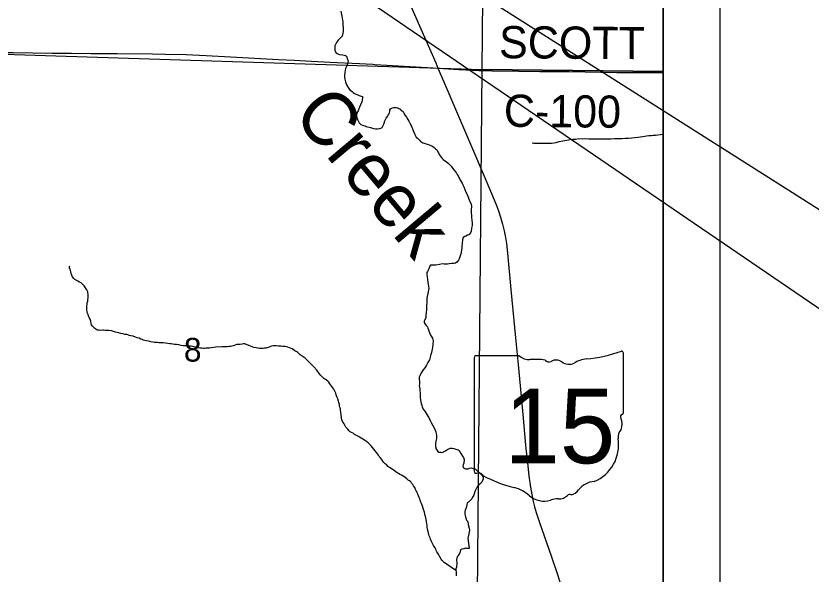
# Model space of a CAD drawing. Extents: x 0 to 34, y 0 to 22.
# Drawn here: x 7.757 to 9.161, y 14.502 to 15.487 of the extents above; entities that cross this region are included whole.
import ezdxf

# ---------------------------------------------------------------- set-up
doc = ezdxf.new("R2010")
doc.units = 0
for name, color, linetype in [('GM_X_County_Road', 7, 'Continuous'), ('GM_X_County_Road_Text', 7, 'Continuous'), ('GM_X_County_Text', 7, 'Continuous'), ('GM_X_Minor_River', 7, 'Continuous'), ('GM_X_Minor_River_Text', 7, 'Continuous'), ('GM_X_Rail_Line_Text', 7, 'Continuous'), ('GM_X_Section', 7, 'Continuous'), ('GM_X_Section_Text', 7, 'Continuous'), ('GM_X_State_Location', 7, 'Continuous'), ('GM_X_State_Route', 7, 'Continuous'), ('GM_X_State_Shield', 7, 'Continuous'), ('GM_X_Township_Road', 7, 'Continuous'), ('SH_Cut_Line', 7, 'Continuous'), ('SH_Data', 7, 'Continuous'), ('TX_P_1', 7, 'Continuous')]:
    doc.layers.add(name, color=color, linetype=linetype)

msp = doc.modelspace()

# ---------------------------------------------------------------- linework, layer by layer
at = {"layer": 'GM_X_County_Road'}
for points in [[(7.5713, 15.4236), (7.5782, 15.4235), (7.5987, 15.4232), (7.6392, 15.4233), (7.6746, 15.4228), (7.7138, 15.4224), (7.7523, 15.422), (7.8207, 15.4213), (7.855, 15.4212), (7.889, 15.4207), (7.9212, 15.4207), (7.9357, 15.4208), (7.9984, 15.42), (8.0208, 15.4192), (8.0575, 15.4185), (8.0929, 15.4171), (8.1357, 15.4146), (8.2207, 15.4099), (8.2487, 15.4086), (8.2791, 15.407), (8.3113, 15.4055)], [(8.3113, 15.4055), (8.3636, 15.4029), (8.3871, 15.4014), (8.3911, 15.4012)], [(8.3911, 15.4012), (8.412, 15.4), (8.4942, 15.395), (8.5024, 15.3946)], [(8.5024, 15.3946), (8.5395, 15.3922), (8.5525, 15.3917), (8.5632, 15.3912), (8.5744, 15.3907), (8.5863, 15.3903), (8.5979, 15.3899), (8.6454, 15.3892), (8.6821, 15.389), (8.7343, 15.3885), (8.8182, 15.3872), (8.8686, 15.3872), (8.8916, 15.3869), (8.9, 15.3868)]]:
    msp.add_lwpolyline(points, dxfattribs=at)
at = {"layer": 'GM_X_County_Text'}
msp.add_lwpolyline([(6.615, 14.1), (8.9, 14.1), (8.9, 16.3981)], dxfattribs=at)
at = {"layer": 'GM_X_Minor_River'}
for points in [[(8.3309, 15.4952), (8.3326, 15.4864), (8.3336, 15.4795), (8.3343, 15.4768), (8.3345, 15.4723), (8.3351, 15.4647), (8.335, 15.4593), (8.3345, 15.4567), (8.3333, 15.451), (8.3302, 15.4481), (8.3278, 15.4458), (8.3263, 15.444), (8.3247, 15.4421), (8.3231, 15.4399), (8.3212, 15.4365), (8.3203, 15.4342), (8.3203, 15.4319), (8.3202, 15.4293), (8.3205, 15.4262), (8.3223, 15.4224), (8.3246, 15.4208), (8.328, 15.4189), (8.3336, 15.418), (8.3367, 15.4175), (8.3389, 15.4171), (8.3408, 15.4159), (8.3425, 15.4098), (8.3436, 15.4078), (8.3419, 15.3999), (8.3391, 15.3943), (8.3378, 15.3871), (8.3373, 15.3818), (8.3376, 15.378), (8.3379, 15.3753), (8.339, 15.3707), (8.3411, 15.3653), (8.3437, 15.3603), (8.3462, 15.3572), (8.3485, 15.3553), (8.3507, 15.3533), (8.3529, 15.3514), (8.3548, 15.3502), (8.3589, 15.3482), (8.3608, 15.3474), (8.3631, 15.3462), (8.365, 15.3458), (8.3668, 15.345), (8.3691, 15.3445), (8.369, 15.3419)], [(8.369, 15.3419), (8.3681, 15.3354), (8.3657, 15.3298), (8.3641, 15.326), (8.3629, 15.3226), (8.3617, 15.3193), (8.3601, 15.3174), (8.3589, 15.3144), (8.3585, 15.3125), (8.3584, 15.3106), (8.3591, 15.3072), (8.3602, 15.3041), (8.3616, 15.3014), (8.3635, 15.2983), (8.3661, 15.2952), (8.3694, 15.294), (8.3717, 15.2932), (8.374, 15.2927), (8.3758, 15.2919), (8.3781, 15.2911), (8.3811, 15.2903), (8.3834, 15.2899), (8.3853, 15.2891), (8.3883, 15.2882), (8.3921, 15.2874), (8.3959, 15.2873), (8.3997, 15.288), (8.4016, 15.2887), (8.4039, 15.2901), (8.4059, 15.2935), (8.4067, 15.2958), (8.4079, 15.2992), (8.4087, 15.3014), (8.4095, 15.3041), (8.4107, 15.3063), (8.4131, 15.3093), (8.4143, 15.3116), (8.4158, 15.3134), (8.417, 15.316), (8.4175, 15.3183), (8.4175, 15.321), (8.4187, 15.3228), (8.4206, 15.3239), (8.4245, 15.325), (8.4286, 15.3253), (8.4313, 15.3245), (8.4332, 15.3236), (8.4354, 15.3221), (8.4376, 15.3201), (8.4395, 15.3186), (8.4413, 15.3166), (8.4428, 15.3143), (8.4446, 15.3112), (8.4468, 15.3081), (8.4494, 15.3039), (8.4512, 15.3008), (8.453, 15.2973), (8.4548, 15.2935), (8.4595, 15.2816), (8.4617, 15.2774), (8.4642, 15.2731), (8.4661, 15.2708), (8.4679, 15.2692), (8.4698, 15.2673), (8.4716, 15.2654), (8.4739, 15.2638), (8.4758, 15.263), (8.478, 15.2622), (8.4818, 15.2609), (8.4859, 15.2597), (8.4886, 15.2589), (8.4908, 15.2577), (8.4927, 15.2569), (8.4957, 15.2545), (8.4979, 15.2522), (8.5002, 15.2506), (8.5023, 15.2472), (8.5034, 15.2452), (8.5045, 15.2422), (8.5064, 15.2398), (8.5078, 15.2375), (8.5097, 15.2352), (8.5115, 15.2336), (8.5141, 15.2317), (8.5171, 15.2301), (8.5205, 15.227), (8.5227, 15.2246), (8.5257, 15.2215), (8.5282, 15.218), (8.5312, 15.2146), (8.5334, 15.2115), (8.5353, 15.2095), (8.5363, 15.2072), (8.5378, 15.2045), (8.5392, 15.2018), (8.5403, 15.1999), (8.5411, 15.198), (8.5451, 15.1914), (8.5462, 15.1887), (8.548, 15.1849), (8.5498, 15.1807)], [(8.669, 15.2626), (8.6694, 15.2626), (8.6716, 15.2625), (8.6758, 15.2624), (8.6796, 15.2623), (8.688, 15.2621), (8.691, 15.2621), (8.6959, 15.262), (8.6997, 15.2622), (8.7032, 15.2625), (8.707, 15.2628), (8.7112, 15.2635), (8.7165, 15.2649), (8.723, 15.2666), (8.7299, 15.2676), (8.736, 15.2686), (8.7413, 15.2692), (8.7458, 15.2695), (8.7512, 15.2702), (8.758, 15.27), (8.7633, 15.2702), (8.769, 15.2701), (8.7751, 15.27), (8.7812, 15.2698), (8.7872, 15.2697), (8.7933, 15.2699), (8.7982, 15.2698), (8.8032, 15.2701), (8.8085, 15.2699), (8.8142, 15.2702), (8.8218, 15.2704), (8.8275, 15.2706), (8.8332, 15.2709), (8.8389, 15.2711), (8.8446, 15.2714), (8.8503, 15.272), (8.8556, 15.273), (8.8602, 15.2737), (8.864, 15.2743), (8.8678, 15.2746), (8.8709, 15.2753), (8.8747, 15.2756), (8.8796, 15.2759), (8.8827, 15.2762), (8.8865, 15.2765), (8.8907, 15.2767), (8.8952, 15.2774), (8.9, 15.2784)], [(8.5498, 15.1807), (8.5515, 15.1757), (8.5541, 15.1715), (8.5559, 15.1672), (8.558, 15.1607), (8.5606, 15.1561), (8.5616, 15.1508), (8.5611, 15.1443), (8.561, 15.1409), (8.5615, 15.1321), (8.5621, 15.1253), (8.5628, 15.1222), (8.5627, 15.1169), (8.5618, 15.112), (8.5613, 15.1067), (8.5597, 15.1037), (8.557, 15.1007), (8.5547, 15.0996), (8.5516, 15.0982), (8.5497, 15.0978), (8.547, 15.0956), (8.5458, 15.0918), (8.5444, 15.0801), (8.5443, 15.0774), (8.5442, 15.0733), (8.5429, 15.0672), (8.5413, 15.0616), (8.5397, 15.0582), (8.5388, 15.0555), (8.5357, 15.0522), (8.5334, 15.0503), (8.5304, 15.05), (8.5269, 15.0497), (8.5224, 15.0491), (8.5193, 15.0488), (8.5167, 15.0488), (8.5136, 15.0489), (8.5106, 15.049), (8.5053, 15.048), (8.4988, 15.047), (8.4931, 15.0471), (8.4893, 15.0472), (8.4881, 15.0453), (8.4861, 15.0404), (8.4837, 15.0359), (8.4825, 15.0341), (8.4828, 15.0299), (8.4835, 15.0261), (8.4841, 15.0215), (8.4848, 15.0162), (8.4851, 15.0131), (8.4858, 15.0097), (8.4861, 15.0062), (8.4856, 15.0032), (8.4851, 14.9998), (8.4826, 14.9888), (8.4829, 14.9866), (8.4828, 14.9812), (8.4823, 14.9748), (8.4821, 14.9683), (8.4816, 14.9634), (8.4812, 14.9592), (8.4807, 14.9547), (8.4794, 14.9502), (8.4782, 14.9479), (8.4782, 14.946), (8.4796, 14.9429), (8.4815, 14.9402), (8.4837, 14.9383), (8.4844, 14.936), (8.489, 14.9233), (8.4927, 14.9183), (8.4941, 14.9133), (8.4927, 14.9016), (8.491, 14.8925), (8.4898, 14.8891), (8.4873, 14.8797), (8.4845, 14.8752), (8.4821, 14.8703), (8.479, 14.8658), (8.4762, 14.8621), (8.4739, 14.8587), (8.4723, 14.8557), (8.4711, 14.8535), (8.4703, 14.8516), (8.4695, 14.8493), (8.4694, 14.8463), (8.4697, 14.8417), (8.4696, 14.8371), (8.4695, 14.8345), (8.4698, 14.8314), (8.4701, 14.8284), (8.4704, 14.8257), (8.4707, 14.8212), (8.4709, 14.8132), (8.4715, 14.8086), (8.4722, 14.8055), (8.4729, 14.8029), (8.474, 14.7998), (8.4747, 14.7967), (8.4765, 14.7925)], [(8.0524, 14.9048), (8.049, 14.9052), (8.0448, 14.9061), (8.0407, 14.9066), (8.0373, 14.907), (8.0339, 14.9075), (8.0312, 14.9079), (8.0286, 14.908), (8.0252, 14.9089), (8.021, 14.9093), (8.0168, 14.9098), (8.013, 14.9099), (8.0096, 14.91), (8.007, 14.9104), (8.0047, 14.9105), (8.0017, 14.9105), (7.9986, 14.911), (7.9952, 14.9118), (7.9933, 14.9119), (7.9911, 14.9127), (7.9869, 14.9136), (7.9824, 14.9148), (7.9798, 14.9156), (7.9775, 14.9164), (7.9749, 14.918), (7.9711, 14.9189), (7.9681, 14.9201), (7.9643, 14.9213), (7.9602, 14.9222), (7.9572, 14.923), (7.9549, 14.9238), (7.9526, 14.9243), (7.9496, 14.9247), (7.9462, 14.9255), (7.9424, 14.9264), (7.9379, 14.9276), (7.9326, 14.9289), (7.9292, 14.9301), (7.9255, 14.931), (7.9213, 14.9315), (7.9179, 14.9315), (7.9145, 14.9316), (7.9118, 14.9321), (7.9099, 14.9321), (7.9069, 14.9314), (7.9042, 14.9319), (7.9012, 14.9323), (7.8986, 14.9335), (7.8956, 14.9355), (7.8937, 14.9374), (7.8919, 14.9398), (7.8904, 14.9417), (7.8901, 14.9436), (7.889, 14.9478), (7.888, 14.9516), (7.8865, 14.9547), (7.8854, 14.9566), (7.8844, 14.9597), (7.883, 14.9635), (7.8826, 14.9654), (7.8823, 14.9673), (7.882, 14.9696), (7.882, 14.9715), (7.8821, 14.9746), (7.8825, 14.978), (7.883, 14.9806), (7.8838, 14.9836), (7.8842, 14.9863), (7.8843, 14.9893), (7.8844, 14.992), (7.8844, 14.9939), (7.8838, 14.9996), (7.882, 15.0034), (7.8798, 15.0069), (7.8776, 15.0104), (7.8746, 15.0131), (7.872, 15.0155), (7.869, 15.0171), (7.8664, 15.0186), (7.8612, 15.0218), (7.8593, 15.0234), (7.8567, 15.0261), (7.8557, 15.0295), (7.8546, 15.0322), (7.8539, 15.0349), (7.8532, 15.0376), (7.8525, 15.0399), (7.8518, 15.0418), (7.8515, 15.0448), (7.8519, 15.0456)], [(8.3365, 14.7666), (8.3347, 14.7693), (8.3325, 14.7735), (8.3322, 14.7777), (8.3316, 14.7826), (8.331, 14.7872), (8.3303, 14.791), (8.33, 14.7941), (8.3293, 14.7964), (8.3286, 14.7987), (8.3282, 14.801), (8.3276, 14.8044), (8.3265, 14.8071), (8.3258, 14.8109), (8.3244, 14.8136), (8.3233, 14.8163), (8.3226, 14.8182), (8.3219, 14.8209), (8.3204, 14.8243), (8.3182, 14.8282), (8.3116, 14.8375), (8.3098, 14.8402), (8.3076, 14.8421), (8.305, 14.8445), (8.3027, 14.8457), (8.3008, 14.8468), (8.2982, 14.8492), (8.2956, 14.8519), (8.2927, 14.8558), (8.2883, 14.8616), (8.2831, 14.8674), (8.2779, 14.8728), (8.2727, 14.8779), (8.2679, 14.883), (8.2623, 14.8861), (8.2589, 14.8889), (8.2567, 14.8908), (8.2548, 14.8928), (8.253, 14.894), (8.2496, 14.8959), (8.2474, 14.8975), (8.2447, 14.8991), (8.2421, 14.9003), (8.2402, 14.9011), (8.2372, 14.9019), (8.2346, 14.9027), (8.2319, 14.9032), (8.2285, 14.9036), (8.2247, 14.9037), (8.221, 14.9042), (8.2168, 14.9043), (8.2137, 14.9044), (8.2115, 14.9044), (8.2084, 14.9037), (8.2057, 14.9027), (8.2027, 14.9016), (8.2, 14.9009), (8.1981, 14.9006), (8.1958, 14.9002), (8.1939, 14.8999), (8.1912, 14.9), (8.1893, 14.9), (8.1871, 14.9001), (8.1844, 14.9005), (8.181, 14.901), (8.1772, 14.9018), (8.1712, 14.9039), (8.1614, 14.9079), (8.1588, 14.9083), (8.1565, 14.9073), (8.1531, 14.907), (8.15, 14.9066), (8.1474, 14.9067), (8.1443, 14.9056), (8.1424, 14.9049), (8.1405, 14.9046), (8.1382, 14.9039), (8.1359, 14.9036), (8.1336, 14.9032), (8.1306, 14.9029), (8.1283, 14.9026), (8.1256, 14.9027), (8.1215, 14.9028), (8.1101, 14.9023), (8.1059, 14.9016), (8.1017, 14.901), (8.0986, 14.9006), (8.0952, 14.9003), (8.0922, 14.9004), (8.0899, 14.9001), (8.0876, 14.9001), (8.0846, 14.9002), (8.0819, 14.9007), (8.0789, 14.9011), (8.0751, 14.902), (8.071, 14.9028), (8.0664, 14.9037), (8.0626, 14.9042), (8.0592, 14.9046), (8.0554, 14.9047), (8.0524, 14.9048)], [(8.4765, 14.7925), (8.4791, 14.789), (8.4809, 14.7863), (8.4827, 14.7836), (8.4846, 14.7806), (8.4864, 14.7778), (8.4889, 14.7725), (8.4911, 14.7679), (8.4933, 14.764), (8.4955, 14.7598), (8.4973, 14.7559), (8.4987, 14.7525), (8.4994, 14.7494), (8.4997, 14.7468), (8.5, 14.7437), (8.4996, 14.7411), (8.4991, 14.7388), (8.4987, 14.7358), (8.4982, 14.7327), (8.4982, 14.7297), (8.4981, 14.727), (8.4984, 14.7251), (8.4988, 14.7232), (8.5021, 14.7182), (8.5039, 14.717), (8.507, 14.7166), (8.5089, 14.7165), (8.5108, 14.7169), (8.5134, 14.7179), (8.5158, 14.7194), (8.5181, 14.7212), (8.5204, 14.7223), (8.5227, 14.7234), (8.5246, 14.7237), (8.5273, 14.7241), (8.5303, 14.7236), (8.5337, 14.722), (8.5378, 14.7208), (8.5397, 14.7196), (8.5426, 14.7146), (8.5455, 14.7099), (8.5477, 14.7072), (8.5488, 14.7038), (8.5479, 14.6977), (8.5471, 14.6947), (8.5466, 14.6924), (8.5473, 14.6894), (8.5511, 14.6874), (8.5537, 14.6873), (8.5556, 14.6877), (8.5583, 14.6887), (8.5617, 14.689), (8.5644, 14.6882), (8.5663, 14.6878), (8.5689, 14.6866), (8.5782, 14.678), (8.5804, 14.6757), (8.5822, 14.6726), (8.5822, 14.6696), (8.5813, 14.6669), (8.5798, 14.6639), (8.5766, 14.6606), (8.5739, 14.6584), (8.5716, 14.6558), (8.5696, 14.652), (8.5676, 14.6475), (8.5656, 14.6411), (8.5636, 14.6373), (8.562, 14.6347), (8.5589, 14.631), (8.5561, 14.6284), (8.5538, 14.6277), (8.5534, 14.6239), (8.5521, 14.6186), (8.5505, 14.6144), (8.5497, 14.6118), (8.55, 14.6072), (8.551, 14.6027), (8.5531, 14.5969), (8.555, 14.5942), (8.5556, 14.5892), (8.5577, 14.5827), (8.558, 14.5793), (8.5571, 14.5729), (8.5559, 14.5676), (8.5554, 14.5653), (8.5573, 14.547), (8.5554, 14.5467), (8.5523, 14.5471), (8.5504, 14.5472), (8.5481, 14.5465), (8.5447, 14.5454), (8.542, 14.5443), (8.5408, 14.5394), (8.538, 14.5342), (8.5356, 14.5304), (8.5352, 14.5266), (8.5358, 14.5209), (8.5352, 14.5141), (8.534, 14.5107), (8.5339, 14.5077)], [(8.5339, 14.5077), (8.5134, 14.5222), (8.5112, 14.5246), (8.5093, 14.5261), (8.5082, 14.528), (8.506, 14.5319), (8.5042, 14.5354), (8.502, 14.5388), (8.5006, 14.5411), (8.4995, 14.5435), (8.4988, 14.5458), (8.4973, 14.5481), (8.4958, 14.5504), (8.4948, 14.5523), (8.4929, 14.5558), (8.4911, 14.5592), (8.4893, 14.5631), (8.4886, 14.5654), (8.4868, 14.5692), (8.4861, 14.5715), (8.4854, 14.5746), (8.4847, 14.5784), (8.4841, 14.5818), (8.4834, 14.5841), (8.4834, 14.586), (8.4831, 14.5879), (8.4827, 14.5906), (8.4814, 14.5982), (8.4807, 14.6009), (8.48, 14.6051), (8.4787, 14.6108), (8.4769, 14.6154), (8.4755, 14.62), (8.4744, 14.6235), (8.4733, 14.6262), (8.4723, 14.6288), (8.4712, 14.6319), (8.4701, 14.6342), (8.4694, 14.6369), (8.4683, 14.6396), (8.4672, 14.6415), (8.4665, 14.6438), (8.4654, 14.6461), (8.464, 14.6484), (8.4629, 14.6511), (8.4615, 14.6542), (8.4593, 14.6576), (8.4578, 14.66), (8.4559, 14.6619), (8.4545, 14.6642), (8.4519, 14.6662), (8.45, 14.6677), (8.4474, 14.6697), (8.4437, 14.6728), (8.4411, 14.6744), (8.4381, 14.6764), (8.4351, 14.6776), (8.4328, 14.6792), (8.4306, 14.6804), (8.428, 14.6823), (8.4257, 14.6839), (8.4231, 14.6859), (8.4205, 14.6874), (8.4179, 14.689), (8.4156, 14.6906), (8.4137, 14.6918), (8.4119, 14.6937), (8.4093, 14.6964), (8.4067, 14.6988), (8.4049, 14.7011), (8.4034, 14.7038), (8.4001, 14.7073), (8.3986, 14.7092), (8.3971, 14.7116), (8.3957, 14.7139), (8.3938, 14.7162), (8.3916, 14.7193), (8.389, 14.7224), (8.3868, 14.7251), (8.3846, 14.7278), (8.3813, 14.7309), (8.379, 14.7333), (8.3761, 14.7356), (8.3727, 14.738), (8.3697, 14.7399), (8.3667, 14.7415), (8.3641, 14.7431), (8.3618, 14.7443), (8.3596, 14.7455), (8.3573, 14.7471), (8.3547, 14.7483), (8.3525, 14.7502), (8.3495, 14.7514), (8.3476, 14.753), (8.3458, 14.7546), (8.3435, 14.7573), (8.3417, 14.7592), (8.3398, 14.7612), (8.3384, 14.7635), (8.3365, 14.7666)], [(8.5339, 14.5077), (8.5343, 14.5054), (8.5346, 14.502), (8.5345, 14.4985)]]:
    msp.add_lwpolyline(points, dxfattribs=at)
at = {"layer": 'GM_X_Rail_Line_Text'}
for points in [[(8.9, 15.3885), (8.9, 16.3968), (8.5987, 16.4027), (8.5893, 16.4029), (8.5798, 15.3924)], [(8.9, 14.393), (8.9, 15.3885), (8.5798, 15.3924), (8.5711, 14.3987)]]:
    msp.add_lwpolyline(points, close=True, dxfattribs=at)
at = {"layer": 'GM_X_Section'}
msp.add_lwpolyline([(7.5704, 15.4246), (8.5798, 15.3924), (8.5711, 14.3987), (7.5551, 14.4246)], close=True, dxfattribs=at)
at = {"layer": 'GM_X_State_Route'}
for points in [[(8.4259, 15.5698), (8.4898, 15.4241), (8.4984, 15.4041), (8.5024, 15.3946), (8.5128, 15.3703), (8.5351, 15.3183), (8.5581, 15.2646), (8.5876, 15.1955)], [(8.5876, 15.1955), (8.6019, 15.1623), (8.6058, 15.1525), (8.6094, 15.1426), (8.6131, 15.1314), (8.6164, 15.1195), (8.6194, 15.1075), (8.6217, 15.0959), (8.6234, 15.0849), (8.6253, 15.0683), (8.6314, 15.0039), (8.6331, 14.986)], [(8.6331, 14.986), (8.6393, 14.9185), (8.6432, 14.8776), (8.6492, 14.8151), (8.6528, 14.7767), (8.6572, 14.729), (8.6578, 14.7231)], [(8.6578, 14.7231), (8.6604, 14.6981), (8.663, 14.6752), (8.6659, 14.6549), (8.6681, 14.642), (8.6707, 14.6298), (8.6731, 14.6201), (8.6759, 14.6105), (8.6811, 14.5946), (8.7028, 14.5323), (8.7129, 14.5029), (8.717, 14.4899), (8.7213, 14.475), (8.7253, 14.4594), (8.7312, 14.4333), (8.7401, 14.3919), (8.7487, 14.3518)]]:
    msp.add_lwpolyline(points, dxfattribs=at)
at = {"layer": 'GM_X_State_Shield'}
for p, q in [((8.8299, 14.787), (8.8299, 14.8916)), ((8.5662, 14.8832), (8.5662, 14.6831)), ((8.646, 14.8867), (8.5688, 14.8867)), ((8.8299, 14.787), (8.8299, 14.787))]:
    msp.add_line(p, q, dxfattribs=at)
for centre, radius, start, end in [((8.736, 15.1595), 0.2796, 275.8445, 288.9065), ((8.827, 14.8921), 0.00294, 351.8621, 97.738), ((8.5692, 14.8837), 0.00305, 98.1301, 188.1301), ((8.6644, 14.9099), 0.0296, 231.6195, 271.1119), ((8.6742, 14.7743), 0.1064, 80.4867, 94.9883), ((8.6984, 14.8847), 0.00855, 219.7921, 297.1024), ((8.7109, 14.8616), 0.0178, 54.4667, 119.1411), ((8.7339, 14.8933), 0.0214, 233.8562, 294.8282), ((8.7716, 14.8256), 0.0563, 97.3462, 120.7689), ((8.8292, 14.7793), 0.00454, 107.944, 210.337), ((8.8003, 14.766), 0.0273, 340.033, 23.6496), ((8.8268, 14.7866), 0.00314, 289.6038, 7.7341), ((8.8404, 14.7431), 0.0198, 136.8065, 186.9296), ((8.7516, 14.7298), 0.0699, 292.3089, 8.9858), ((8.5693, 14.6827), 0.00308, 171.9584, 258.3066), ((8.5697, 14.7032), 0.0235, 267.339, 280.6039), ((8.5746, 14.6716), 0.00848, 29.7484, 93.2717), ((8.6816, 14.8514), 0.2019, 240.4129, 257.1985), ((8.7811, 14.6269), 0.0383, 94.4031, 142.5768), ((8.6214, 14.5932), 0.0632, 47.1842, 75.836), ((8.7326, 14.6637), 0.0226, 282.8732, 323.2771), ((8.6897, 14.6706), 0.0401, 230.7004, 286.2918), ((8.7158, 14.6556), 0.0214, 268.777, 315.5493), ((8.7352, 14.6362), 0.00601, 65.7517, 132.6484), ((8.7129, 14.6014), 0.0329, 85.6951, 111.2099)]:
    msp.add_arc(centre, radius, start, end, dxfattribs=at)
at = {"layer": 'GM_X_Township_Road'}
for points in [[(7.5713, 15.4236), (7.5782, 15.4235), (7.5987, 15.4232), (7.6392, 15.4233), (7.6746, 15.4228), (7.7138, 15.4224), (7.7523, 15.422), (7.8207, 15.4213), (7.855, 15.4212), (7.889, 15.4207), (7.9212, 15.4207), (7.9357, 15.4208), (7.9984, 15.42), (8.0208, 15.4192), (8.0575, 15.4185), (8.0929, 15.4171), (8.1357, 15.4146), (8.2207, 15.4099), (8.2487, 15.4086), (8.2791, 15.407), (8.3113, 15.4055)], [(8.3113, 15.4055), (8.3636, 15.4029), (8.3871, 15.4014), (8.3911, 15.4012)], [(8.3911, 15.4012), (8.412, 15.4), (8.4942, 15.395), (8.5024, 15.3946)]]:
    msp.add_lwpolyline(points, dxfattribs=at)
at = {"layer": 'SH_Cut_Line'}
msp.add_lwpolyline([(2.1, 16.5239), (2.1, 14.1), (8.9, 14.1), (8.9, 16.3981)], dxfattribs=at)
at = {"layer": 'SH_Data'}
for p, q in [((9, 21), (9, 14)), ((8.9, 20.9), (8.9, 14.1))]:
    msp.add_line(p, q, dxfattribs=at)
at = {"layer": 'TX_P_1'}
msp.add_lwpolyline([(9.2734, 14.9035), (5.5187, 17.4627), (9.2734, 15.0836)], close=True, dxfattribs=at)

# ---------------------------------------------------------------- texts
at = {"layer": 'GM_X_County_Road_Text'}
for s, rotation, p in [('SCOTT', 359.5674, (8.6102, 15.4123)), ('C-100', 359.4499, (8.6186, 15.2913))]:
    msp.add_text(s, height=0.05682, rotation=rotation, dxfattribs=at).set_placement(p)
at = {"layer": 'GM_X_Minor_River_Text'}
msp.add_text('Creek', height=0.09476, rotation=310.0429, dxfattribs=at).set_placement((8.2436, 15.3116))
at = {"layer": 'GM_X_Section_Text'}
msp.add_text('8', height=0.0419, rotation=0, dxfattribs=at).set_placement((8.0536, 14.8767))
at = {"layer": 'GM_X_State_Location'}
for s in ['s', 'r']:
    msp.add_text(s, height=0.000189, dxfattribs=at).set_placement((8.6951, 14.7699))
msp.add_text('15', height=0.000189, rotation=0, dxfattribs=at).set_placement((8.6474, 14.7561))
at = {"layer": 'GM_X_State_Shield'}
msp.add_text('15', height=0.13184, dxfattribs=at).set_placement((8.6195, 14.6972))

doc.saveas('drawing.dxf')
